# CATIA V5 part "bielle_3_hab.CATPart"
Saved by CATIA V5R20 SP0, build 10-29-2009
Part number: bielle_3_hab
Bounding box of the stored display mesh (mm): x 0.05 to 0.1, y 0.86 to 2.5, z -0.1 to 2.73
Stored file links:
  D:\Dropbox\IAO_2012\IAO_2012_718_ccascaro\ccascaro\bielle_3_hab.CATPart
  C:\Users\Cédric\Documents\IFMA-2A\IAO\Projet IAO\Projet IAO catia\ass_bielles_skl.CATProduct
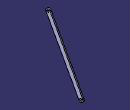
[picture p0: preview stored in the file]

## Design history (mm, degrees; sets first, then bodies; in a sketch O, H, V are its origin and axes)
Set1
  Point1 "point C": linked copy from another document
  Point2 "point D": linked copy from another document
Body1 (main body)
  Sketch1 on yz-plane, origin (0, 0, 0), H (0, 1, 0), V (0, 0, 1)
    construction line L1 (0.96, 2.63) -> (2.4, 0)
    point P1 (0.96, 2.63)
    point P2 (2.4, 0)
    line L2 (1.0477, 2.678) -> (2.4877, 0.048)
    line L3 (2.3123, -0.048) -> (0.8723, 2.582)
    arc A1 centre (2.4, 0) radius 0.1 from (2.4877, 0.048) to (2.3123, -0.048) cw
    arc A2 centre (0.96, 2.63) radius 0.1 from (0.8723, 2.582) to (1.0477, 2.678) cw
    reference projected point E1 (0.96, 2.63) from Point1
    reference projected point E2 (2.4, 0) from Point2
    circle A3 centre (2.4, 0) radius 0.05
    circle A4 centre (0.96, 2.63) radius 0.05
    distance L1 L2 = 0.1
    distance P1 E1 = 0
    distance P2 E2 = 0
    tangency: A1 L2, A2 L2, A1 L3, A2 L3
  Pad1: profile Sketch1, direction (1, 0, 0), length 0.1, opposite side length -0.05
